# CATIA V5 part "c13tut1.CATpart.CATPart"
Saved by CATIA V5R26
Part number: Part1
Bounding box of the stored display mesh (mm): x -49.812 to 35, y -44.222 to 44.222, z 0 to 30
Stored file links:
  D:\_Deepak\CATIA\CATIA V5 2015 Parts Files\Tutorial Files\Tutorials\c13_catia_v5_6r2016_tut\c13tut1\c13tut1.CATpart.CATPart
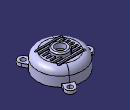
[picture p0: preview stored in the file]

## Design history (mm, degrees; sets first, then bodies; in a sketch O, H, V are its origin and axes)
Body1 (main body)
  Sketch1 on yz-plane, origin (0, 0, 0), H (0, 1, 0), V (0, 0, 1)
    line L1 (0, 0) -> (35, 0)
    line L2 (35, 0) -> (35, 15)
    arc A1 centre (25, 15) radius 10 from (35, 15) to (25, 25) ccw
    line L3 (25, 25) -> (0, 25)
    point P5 (0, 25)
    line L4 (0, 25) -> (0, 0)
    axis line L5 (0, 70.1891) -> (0, -36.6898)
    point P6 (0, 70.1891)
    radius about axis L2 L5 = 35
    distance L1 L3 = 25
    radius A1 = 10
    horizontal: L1 H
    vertical: L2 V, L4 V, L5 V
    tangency: A1 L2, L3 A1
    coincidence: P5 V, P6 V
  Shaft1: profile Sketch1, axis Sketch1.L5, angle 360
  Shell1: ExtOffset 0, Face face of Shaft1, IntOffset 2.5
  Sketch2 on face of Shaft1, origin (0, 0, 0), H (1, 0, 0), V (0, -1, 0)
    projected circle E1 centre (0, 0) radius 35 from edge [face of Shaft1 | face of Shaft1]
    projected arc E2 centre (0, 0) radius 35 from (-34.187, 7.5) to (-34.187, -7.5) ccw from edge [face of Shaft1 | face of Shaft1]
    point P1 (-34.187, 7.5)
    line L1 (-34.187, 7.5) -> (-42.5, 7.5)
    arc A1 centre (-42.5, 0) radius 7.5 from (-42.5, 7.5) to (-42.5, -7.5) ccw
    point P3 (-42.5, 0)
    line L2 (-42.5, -7.5) -> (-34.187, -7.5)
    point P5 (-34.187, -7.5)
    circle A2 centre (-42.5, 0) radius 3.75
    distance P3 V = 42.5
    radius A1 = 7.5
    radius A2 = 3.75
    coincidence: P1 E1, P5 E1, P3 H
    horizontal: L1 H, L2 H
    tangency: A1 L1, L2 A1
  Pad1: profile Sketch2, direction (0, 0, 1), length 5
  CircPattern1: of Pad1, instances 3, angular step 120 {= 360.0*1 deg/CircPattern1.AngularNumber}, axis from face of Shaft1
  Sketch3 on face of Shaft1, origin (0, 0, 25), H (1, 0, 0), V (0, 1, 0)
    construction line L1 (-20, -18) -> (20, -18)
    point P2 (20, -18)
    line L2 (-20, -16.25) -> (20, -16.25)
    line L3 (20, -19.75) -> (-20, -19.75)
    arc A1 centre (20, -18) radius 1.75 from (20, -16.25) to (20, -19.75) cw
    arc A2 centre (-20, -18) radius 1.75 from (-20, -19.75) to (-20, -16.25) cw
    length L1 = 40
    distance H L1 = 18
    distance P2 V = 20
    distance L3 L2 = 3.5
    horizontal: L1 H
    tangency: A1 L2, A2 L2, A1 L3, A2 L3
    parallelism: L1 L2
  Pocket1: profile Sketch3, direction (0, 0, -1), through (limit type 3)
  RectPattern1: of Pocket1, direction 1 instances 7, spacing 6, along yz-plane
  Sketch4 on yz-plane, origin (0, 0, 0), H (0, 1, 0), V (0, 0, 1)
    axis line L1 (0, 0) -> (0, 35.5018)
    point P2 (0, 22.5)
    line L2 (0, 22.5) -> (12.5, 22.5)
    line L3 (12.5, 22.5) -> (12.5, 28)
    arc A1 centre (10.5, 28) radius 2 from (12.5, 28) to (10.5, 30) ccw
    line L4 (10.5, 30) -> (0, 30)
    point P7 (0, 30)
    line L5 (0, 30) -> (0, 22.5)
    reference intersected line E1 (25, 22.5) -> (-25, 22.5) from face of Shell1
    radius about axis L3 L1 = 12.5
    distance L4 L2 = 7.5
    radius A1 = 2
    vertical: L1 V, L3 V, L5 V
    coincidence: P2 L1, P7 L1, L2 E1
    horizontal: L2 H, L4 H
    tangency: A1 L3, L4 A1
  Shaft2: profile Sketch4, axis Sketch4.L1, angle 360
  Sketch5 on face of Shaft2, origin (0, 0, 30), H (1, 0, 0), V (0, 1, 0)
    point P1 (0, 0)
    reference projected circle E1 centre (0, 0) radius 12.5 from edge [face of Shaft2 | face of Shaft2]
    concentricity: P1 E1
  Hole1: placed by Sketch5, at (0, 0, 30) direction (0, 0, -1), diameter 15, through (limit type 3)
